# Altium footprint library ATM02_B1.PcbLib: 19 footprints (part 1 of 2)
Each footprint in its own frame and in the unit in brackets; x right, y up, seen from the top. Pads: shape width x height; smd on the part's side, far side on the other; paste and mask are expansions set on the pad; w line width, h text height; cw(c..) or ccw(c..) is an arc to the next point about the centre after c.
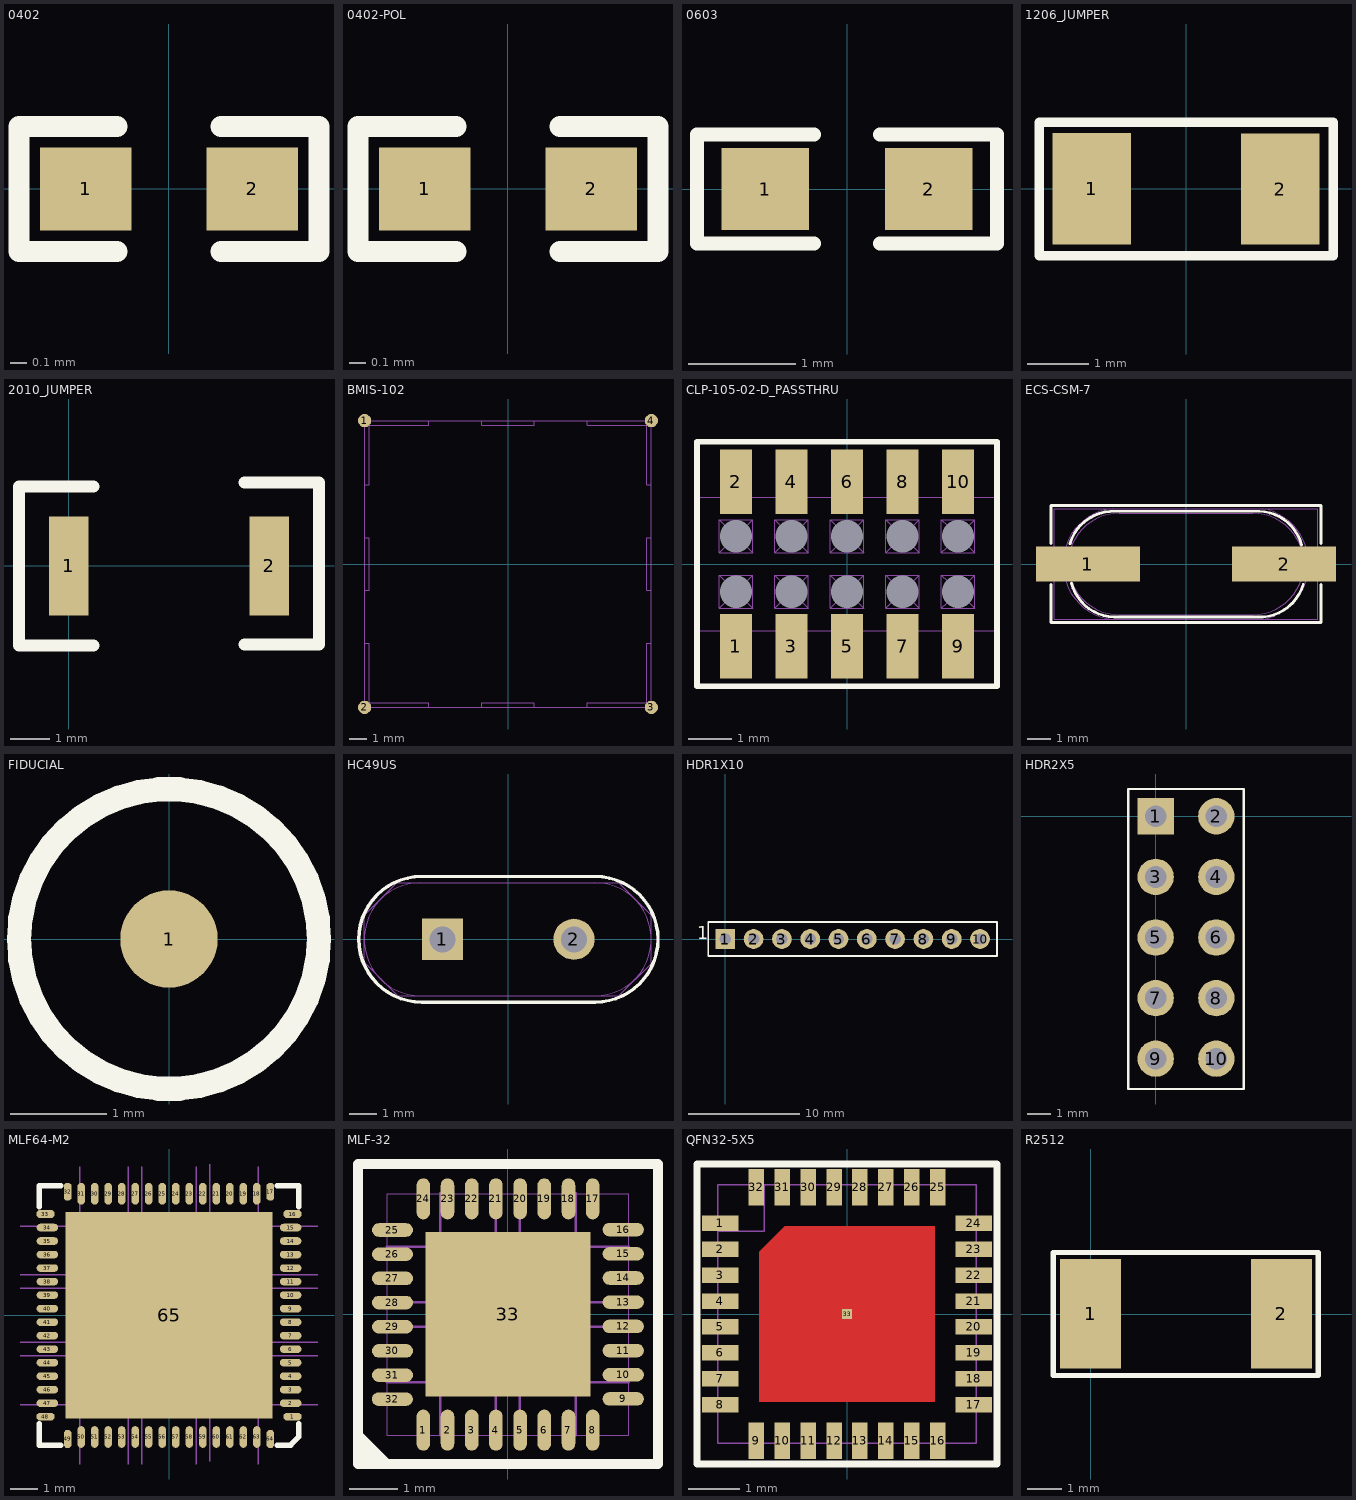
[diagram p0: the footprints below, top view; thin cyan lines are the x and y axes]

## 0402 [mil]
pads (2):
  rect 22x20 smd: 1(-20,0) 2(20,0)
Top Overlay:
  lines w5: -12.5,-15 -36,-15 -36,15 -12.5,15 ; 12.5,-15 36,-15 36,15 12.5,15

## 0402-POL [mil]
pads (2):
  rect 22x20 smd: 1(-20,0) 2(20,0)
Top Overlay:
  lines w5: -36,-10 -36,10 ; -12.5,-15 -36,-15 -36,15 -12.5,15 ; 12.5,-15 36,-15 36,15 12.5,15

## 0603 [mil]
pads (2):
  rect 32x30 smd: 1(-30,0) 2(30,0)
Top Overlay:
  lines w5: -12,-20 -55,-20 -55,20 -12,20 ; 12,-20 55,-20 55,20 12,20

## 1206_JUMPER [mm]
pads (2):
  rect 1.27x1.8 smd: 1(-1.528,0.001) 2(1.528,-0.001)
Top Overlay:
  lines w0.152: -2.379,-1.081 -2.379,1.079 2.381,1.079 2.381,-1.081 -2.379,-1.081

## 2010_JUMPER [mil]
pads (2):
  rect 40x100 smd: 1(0,0) 2(202,0)
Top Overlay:
  lines w12: 25,-80 -50,-80 -50,80 25,80 ; 177,-79 252,-79 252,84 177,84

## BMIS-102 [mil]
pads (4):
  round 30 smd: 1(-325,325) 2(-325,-325) 3(325,-325) 4(325,325)
Top Solder:
  lines w40: -325,-185 -325,-325 -185,-325 ; -325,-55 -325,55 ; -325,185 -325,325 -185,325 ; -55,-325 55,-325 ; -55,325 55,325 ; 185,-325 325,-325 325,-185 ; 185,325 325,325 325,185 ; 325,-55 325,55
Mechanical 1:
  lines w1: -325,-325 325,-325 ; -325,-325 -325,325 ; -325,-325 -325,-180 -315,-180 -315,-315 -180,-315 -180,-325 -325,-325 ; -325,325 325,325 ; -325,325 -180,325 -180,315 -315,315 -315,180 -325,180 -325,325 ; 325,-325 325,325 ; 325,-325 325,-180 315,-180 315,-315 180,-315 180,-325 325,-325 ; 325,325 325,180 315,180 315,315 180,315 180,325 325,325 ; -325,-60 -315,-60 -315,60 -325,60 -325,-60 ; -60,-325 -60,-315 60,-315 60,-325 -60,-325 ; -60,315 -60,325 60,325 60,315 -60,315 ; 315,-60 325,-60 325,60 315,60 315,-60
  text "SHD1" at -273.81,338.25 h22.5
Mechanical 16:
  lines w1: -325,-325 325,-325 325,325 -325,325 -325,-325

## CLP-105-02-D_PASSTHRU [mil]
pads (20):
  rect 29x58 smd: 1(-100,-74) 2(-100,74) 3(-50,-74) 4(-50,74) 5(0,-74) 6(0,74) 7(50,-74) 8(50,74) 9(100,-74) 10(100,74)
  round 0 hole 29 unplated: 11(-100,25) 12(-100,-25) 13(-50,25) 14(-50,-25) 15(0,25) 16(0,-25) 17(50,25) 18(50,-25) 19(100,25) 20(100,-25)
Top Overlay:
  lines w5: -135,-110 -135,110 135,110 135,-110 -135,-110
Mechanical 1:
  drawing of 164 lines, arcs and shapes, not listed
  text "J1" at -6.43,121.25 h22.5
Mechanical 16:
  lines w1: -135,-60 -135,60 135,60 135,-60 -135,-60

## ECS-CSM-7 [mm]
pads (2):
  rect 4.5x1.5 smd: 1(-4.25,0) 2(4.25,0)
Top Overlay:
  lines w0.127: -5.842,-0.889 -5.842,-2.54 5.842,-2.54 5.842,-0.889 ; -5.842,0.889 -5.842,2.54 5.842,2.54 5.842,0.889 ; -5.031,0.876 cw(c-3.14,0.316) -3.047,2.286 3.175,2.286 ; -4.958,-0.834 ccw(c-3.062,-0.34) -3.127,-2.298 ; -3.126,-2.298 3.097,-2.298 ccw(c3.19,-0.329) 5.08,-0.889 ; 3.174,2.286 cw(c3.112,0.329) 5.006,0.826
Mechanical 1:
  lines w0.025: -5.7,-0.4 -6.2,-0.4 -6.2,0.4 -5.7,0.4 ; -3.203,2.4 ccw(c-2.917,0) -3.199,-2.4 ; -3.2,-2.4 3.3,-2.4 ; -3.2,2.4 3.3,2.4 ; 3.297,-2.4 ccw(c2.882,0) 3.301,2.4 ; 5.7,-0.4 6.2,-0.4 6.2,0.4 5.7,0.4 ; -5.7,-2.4 5.7,-2.4 5.7,2.4 -5.7,2.4 -5.7,-2.4 ; -2.9,-2.2 cw(c-2.9,0) -2.9,2.2 2.9,2.2 cw(c2.9,0) 2.9,-2.2 -2.9,-2.2
  text "X2" at 0.558,-0.171 h0.57
Mechanical 16:
  lines w0.025: -5.7,-2.4 5.7,-2.4 5.7,2.4 -5.7,2.4 -5.7,-2.4

## FIDUCIAL [mil]
pads (1):
  round 40 smd mask+40: 1(0,0)
Top Overlay:
  circle w10: c0,0 r61.62

## HC49US [mil]
pads (2):
  rect 60x60 hole 38 unplated: 1(-96.46,0)
  round 60 hole 38 unplated: 2(95.67,0)
Top Overlay:
  lines w5: -126.77,-91.73 cw(c-126.77,0) -126.77,91.73 126.77,91.73 cw(c126.77,0) 126.77,-91.73 -126.77,-91.73
Mechanical 1:
  lines w1: -127.95,-90.94 cw(c-127.95,0.79) -127.95,92.52 125.59,92.52 cw(c125.59,0.79) 125.59,-90.94 -127.95,-90.94 ; -127.95,-82.68 cw(c-127.95,0) -127.95,82.68 125.98,82.68 cw(c125.98,0) 125.98,-82.68 -127.95,-82.68
  text "X1" at -38.19,-11.75 h22.5
Mechanical 16:
  lines w1: -210.63,-33.46 -210.63,35.43 -163.39,82.68 161.42,82.68 208.66,35.43 208.66,-35.43 161.42,-82.68 -161.42,-82.68 -210.63,-33.46

## HDR1X10 [mil] "HDR1X10"
pads (10):
  rect 70x70 hole 40: 1(0,0)
  round 70 hole 40: 2(100,0) 3(200,0) 4(300,0) 5(400,0) 6(500,0) 7(600,0) 8(700,0) 9(800,0) 10(900,0)
Top Overlay:
  lines w6: -60,-60 960,-60 960,60 -60,60 -60,-60
  text "1" at -100,0 h45

## HDR2X5 [mil]
height 43.31
pads (10):
  rect 60x60 hole 36: 1(0,0)
  round 60 hole 36: 2(100,0) 3(0,-100) 4(100,-100) 5(0,-200) 6(100,-200) 7(0,-300) 8(100,-300) 9(0,-400) 10(100,-400)
Top Overlay:
  lines w3.94: -45,-450 -45,45 145,45 145,-450 -45,-450

## MLF64-M2 [mm]
height 0.203
pads (65):
  oct 0.66x0.28 smd paste-0.03 mask+0: 1(4.572,-3.75) 16(4.572,3.75) 33(-4.572,3.75) 48(-4.572,-3.75)
  oval 0.8x0.28 smd paste-0.03 mask+0: 2(4.5,-3.25) 3(4.5,-2.75) 4(4.5,-2.25) 5(4.5,-1.75) 6(4.5,-1.25) 7(4.5,-0.75) 8(4.5,-0.25) 9(4.5,0.25) 10(4.5,0.75) 11(4.5,1.25) 12(4.5,1.75) 13(4.5,2.25) 14(4.5,2.75) 15(4.5,3.25) 34(-4.5,3.25) 35(-4.5,2.75) 36(-4.5,2.25) 37(-4.5,1.75) 38(-4.5,1.25) 39(-4.5,0.75) 40(-4.5,0.25) 41(-4.5,-0.25) 42(-4.5,-0.75) 43(-4.5,-1.25) 44(-4.5,-1.75) 45(-4.5,-2.25) 46(-4.5,-2.75) 47(-4.5,-3.25)
  oct 0.28x0.66 smd paste-0.03 mask+0: 17(3.75,4.572) 32(-3.75,4.572) 49(-3.75,-4.572) 64(3.75,-4.572)
  oval 0.28x0.8 smd paste-0.03 mask+0: 18(3.25,4.5) 19(2.75,4.5) 20(2.25,4.5) 21(1.75,4.5) 22(1.25,4.5) 23(0.75,4.5) 24(0.25,4.5) 25(-0.25,4.5) 26(-0.75,4.5) 27(-1.25,4.5) 28(-1.75,4.5) 29(-2.25,4.5) 30(-2.75,4.5) 31(-3.25,4.5) 50(-3.25,-4.5) 51(-2.75,-4.5) 52(-2.25,-4.5) 53(-1.75,-4.5) 54(-1.25,-4.5) 55(-0.75,-4.5) 56(-0.25,-4.5) 57(0.25,-4.5) 58(0.75,-4.5) 59(1.25,-4.5) 60(1.75,-4.5) 61(2.25,-4.5) 62(2.75,-4.5) 63(3.25,-4.5)
  rect 7.65x7.65 smd paste-2.8 mask+0: 65(0,0)
Top Overlay:
  lines w0.2: -4.8,-4.01 -4.8,-4.8 -4.01,-4.8 ; -4.8,4.01 -4.8,4.8 -4.01,4.8 ; 4.01,-4.8 4.5,-4.8 4.8,-4.5 4.8,-4.01 ; 4.01,4.8 4.8,4.8 4.8,4.01
Top Paste:
  rectangle: -1,1.5 1,3.3
  rectangle: -1,-3.3 1,-1.5
  rectangle: 1.5,-1 3.3,1
  rectangle: -3.3,-1 -1.5,1
  rectangle: -3.3,1.5 -1.5,3.3
  rectangle: 1.5,1.5 3.3,3.3
  rectangle: 1.5,-3.3 3.3,-1.5
  rectangle: -3.3,-3.3 -1.5,-1.5
Mechanical 1:
  lines w0.05: -5.5,-3.3 5.5,-3.3 ; -5.5,-1.5 5.5,-1.5 ; -5.5,-1 5.5,-1 ; -5.5,1 5.5,1 ; -5.5,1.5 5.5,1.5 ; -5.5,3.3 5.5,3.3 ; -3.3,-5.5 -3.3,5.5 ; -1.5,-5.5 -1.5,5.5 ; -1,-5.5 -1,5.5 ; 1,-5.5 1,5.5 ; 1.5,-5.4 1.5,5.6 ; 3.3,-5.5 3.3,5.5

## MLF-32 [mm] "MLF-32 solder foot print"
height 1.016
pads (33):
  oval 0.28x0.85 smd paste-0.03 mask+0: 1(-1.746,-2.39) 2(-1.246,-2.39) 3(-0.746,-2.39) 4(-0.246,-2.39) 5(0.254,-2.39) 6(0.754,-2.39) 7(1.254,-2.39) 8(1.754,-2.39) 17(1.754,2.39) 18(1.254,2.39) 19(0.754,2.39) 20(0.254,2.39) 21(-0.246,2.39) 22(-0.746,2.39) 23(-1.246,2.39) 24(-1.746,2.39)
  oval 0.85x0.28 smd paste-0.03 mask+0: 9(2.386,-1.746) 10(2.386,-1.246) 11(2.386,-0.746) 12(2.386,-0.246) 13(2.386,0.254) 14(2.386,0.754) 15(2.386,1.254) 16(2.386,1.754) 25(-2.383,1.746) 26(-2.383,1.246) 27(-2.383,0.746) 28(-2.383,0.246) 29(-2.383,-0.254) 30(-2.383,-0.754) 31(-2.383,-1.254) 32(-2.386,-1.75)
  rect 3.4x3.4 smd paste-1.7 mask+0: 33(0.004,0)
Top Overlay:
  lines w0.2: -3.096,-2.76 -2.766,-3.09 ; -3.096,-2.49 -2.496,-3.09 ; -3.096,-3.09 3.104,-3.09 3.104,3.11 -3.096,3.11 -3.096,-3.09
Top Paste:
  rectangle: -1.4,0.25 -0.25,1.4
  rectangle: 0.25,0.25 1.4,1.4
  rectangle: -1.4,-1.4 -0.25,-0.25
  rectangle: 0.25,-1.4 1.4,-0.25
Mechanical 1:
  lines w0.02: -2.496,-2.5 -2.496,2.5 2.504,2.5 2.504,-2.5 ; -2.496,-2.497 2.504,-2.497
  lines w0.05: -2.504,-1.4 2.496,-1.4 ; -2.504,1.4 2.496,1.4 ; -2.496,-0.25 2.504,-0.25 ; -2.496,0.25 2.504,0.25 ; -1.4,-2.496 -1.4,2.504 ; -0.25,-2.496 -0.25,2.504 ; 0.25,-2.496 0.25,2.504 ; 1.4,-2.496 1.4,2.504

## QFN32-5X5 [mm]
pads (33):
  rect 0.7x0.3 smd: 1(-2.45,1.75) 2(-2.45,1.25) 3(-2.45,0.75) 4(-2.45,0.25) 5(-2.45,-0.25) 6(-2.45,-0.75) 7(-2.45,-1.25) 8(-2.45,-1.75) 17(2.45,-1.75) 18(2.45,-1.25) 19(2.45,-0.75) 20(2.45,-0.25) 21(2.45,0.25) 22(2.45,0.75) 23(2.45,1.25) 24(2.45,1.75)
  rect 0.3x0.7 smd: 9(-1.75,-2.45) 10(-1.25,-2.45) 11(-0.75,-2.45) 12(-0.25,-2.45) 13(0.25,-2.45) 14(0.75,-2.45) 15(1.25,-2.45) 16(1.75,-2.45) 25(1.75,2.45) 26(1.25,2.45) 27(0.75,2.45) 28(0.25,2.45) 29(-0.25,2.45) 30(-0.75,2.45) 31(-1.25,2.45) 32(-1.75,2.45)
  rect 0.2x0.2 smd: 33(0,0)
Top Layer:
  region: -1.7,1.2 -1.2,1.7 1.7,1.7 1.7,-1.7 -1.7,-1.7
Top Overlay:
  lines w0.127: -2.9,-2.9 2.9,-2.9 2.9,2.9 -2.9,2.9 -2.9,-2.9
Top Paste:
  region: -0.3,0.3 0.3,0.3 0.3,-0.3 -0.3,-0.3
  region: -0.3,-0.6 0.3,-0.6 0.3,-1.2 -0.3,-1.2
  region: -0.3,1.2 0.3,1.2 0.3,0.6 -0.3,0.6
  region: 0.6,1.2 1.2,1.2 1.2,0.6 0.6,0.6
  region: 0.6,0.3 1.2,0.3 1.2,-0.3 0.6,-0.3
  region: 0.6,-0.6 1.2,-0.6 1.2,-1.2 0.6,-1.2
  region: -1.2,-0.6 -0.6,-0.6 -0.6,-1.2 -1.2,-1.2
  region: -1.2,0.3 -0.6,0.3 -0.6,-0.3 -1.2,-0.3
  region: -1.2,1.2 -0.6,1.2 -0.6,0.6 -1.2,0.6
Mechanical 1:
  lines w0.025: -2.5,-2.5 2.5,-2.5 2.5,2.5 -2.5,2.5 -2.5,-2.5
  lines w0.026: -2.5,1.6 -1.6,1.6 -1.6,2.5 -2.5,2.5 -2.5,1.6
  text "U1" at -1.016,-1.651 h0.57
Mechanical 16:
  lines w0.025: -2.5,-2.5 2.5,-2.5 2.5,2.5 -2.5,2.5 -2.5,-2.5

## R2512 [mm]
pads (2):
  rect 1.8x3.2 smd: 1(-0.002,0.012) 2(5.598,0.012)
Top Overlay:
  lines w0.152: 6.678,-1.797 -1.094,-1.791 -1.094,1.805 6.678,1.805 6.678,-1.791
